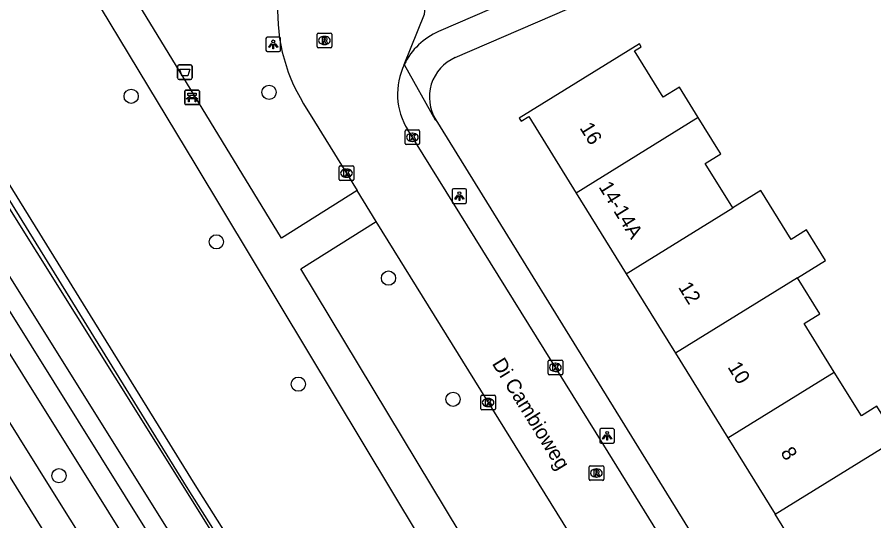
# Model space of a CAD drawing. Extents: x 159353 to 160616, y 385893 to 387321.
# Drawn here: x 159487.8 to 159546.6, y 386184 to 386218.6 of the extents above; entities that cross this region are included whole.
import ezdxf

# ---------------------------------------------------------------- set-up
doc = ezdxf.new("R2010")
doc.units = 0
for name, color, linetype in [('IMGEO_Afvalbak', 7, 'Continuous'), ('IMGEO_Bank', 7, 'Continuous'), ('IMGEO_Boom', 7, 'Continuous'), ('IMGEO_Fietspad_gesloten', 7, 'Continuous'), ('IMGEO_Haag', 7, 'Continuous'), ('IMGEO_Kolk', 7, 'Continuous'), ('IMGEO_Lichtpunt', 7, 'Continuous'), ('IMGEO_Openbare_ruimte_label', 7, 'Continuous'), ('IMGEO_Pand', 7, 'Continuous'), ('IMGEO_Pand_nummerreeks', 7, 'Continuous'), ('IMGEO_Rijbaan_lokaal_open', 7, 'Continuous'), ('IMGEO_Rioolput', 7, 'Continuous'), ('IMGEO_Voetpad_halfverhard', 7, 'Continuous'), ('IMGEO_Voetpad_open', 7, 'Continuous'), ('IMGEO_Waterloop', 7, 'Continuous')]:
    doc.layers.add(name, color=color, linetype=linetype)

msp = doc.modelspace()

# ---------------------------------------------------------------- linework, layer by layer
at = {"layer": 'IMGEO_Afvalbak'}
for p, q in [((159498.825, 386214.38), (159498.825, 386215.18)), ((159498.825, 386215.18), (159498.825, 386214.38)), ((159498.925, 386215.28), (159499.715, 386215.28)), ((159499.715, 386215.28), (159498.925, 386215.28)), ((159499.815, 386215.18), (159499.815, 386214.38)), ((159499.815, 386214.38), (159499.815, 386215.18)), ((159499.715, 386214.28), (159498.925, 386214.28)), ((159498.925, 386214.28), (159499.715, 386214.28))]:
    msp.add_line(p, q, dxfattribs=at)
msp.add_lwpolyline([(159498.968, 386214.994), (159499.672, 386214.994), (159499.523, 386214.524), (159499.117, 386214.524), (159498.968, 386214.994)], dxfattribs=at)
for centre, start, end in [((159498.925, 386215.18), 90, 180), ((159498.925, 386215.18), 90, 180), ((159499.715, 386215.18), 0, 90), ((159499.715, 386215.18), 360, 90), ((159498.925, 386214.38), 180, 270), ((159498.925, 386214.38), 180, 270), ((159499.715, 386214.38), 270, 0), ((159499.715, 386214.38), 270, 0)]:
    msp.add_arc(centre, 0.1, start, end, dxfattribs=at)
at = {"layer": 'IMGEO_Bank'}
for p, q in [((159499.318, 386212.627), (159499.318, 386213.468)), ((159499.318, 386213.468), (159499.318, 386212.627)), ((159499.393, 386213.552), (159500.234, 386213.552)), ((159500.234, 386213.552), (159499.393, 386213.552)), ((159500.318, 386213.477), (159500.318, 386212.636)), ((159500.318, 386212.636), (159500.318, 386213.477)), ((159500.015, 386212.95), (159499.622, 386212.95)), ((159499.627, 386213.058), (159499.627, 386213.164)), ((159499.671, 386213.164), (159499.671, 386213.058)), ((159499.959, 386213.17), (159499.677, 386213.17)), ((159499.677, 386213.052), (159499.959, 386213.052)), ((159499.965, 386213.058), (159499.965, 386213.164)), ((159500.009, 386213.164), (159500.009, 386213.058)), ((159500.243, 386212.552), (159499.402, 386212.552)), ((159499.402, 386212.552), (159500.243, 386212.552))]:
    msp.add_line(p, q, dxfattribs=at)
for points in [[(159499.621, 386213.17), (159499.535, 386213.17), (159499.535, 386213.331), (159500.098, 386213.331), (159500.098, 386213.17), (159500.015, 386213.17)], [(159499.565, 386212.95), (159499.423, 386212.95), (159499.535, 386213.052), (159499.621, 386213.052)], [(159499.615, 386212.943), (159499.615, 386212.736), (159499.572, 386212.736), (159499.572, 386212.943)], [(159500.015, 386213.052), (159500.098, 386213.052), (159500.21, 386212.95), (159500.071, 386212.95)], [(159500.065, 386212.943), (159500.065, 386212.736), (159500.021, 386212.736), (159500.021, 386212.943)]]:
    msp.add_lwpolyline(points, dxfattribs=at)
for centre, radius, start, end in [((159499.396, 386213.474), 0.0779, 92.4484, 184.28452), ((159499.396, 386213.474), 0.0779, 92.4484, 184.28452), ((159500.24, 386213.474), 0.0779, 2.4484, 94.28452), ((159500.24, 386213.474), 0.0779, 2.4484, 94.28452), ((159499.565, 386212.943), 0.00671, 2.89567, 87.10433), ((159499.622, 386212.943), 0.00671, 92.89567, 177.10433), ((159499.62, 386213.163), 0.00671, 2.89567, 87.10433), ((159499.62, 386213.059), 0.00671, 272.89567, 357.10433), ((159499.677, 386213.163), 0.00671, 92.89567, 177.10433), ((159499.677, 386213.059), 0.00671, 182.89567, 267.10433), ((159499.959, 386213.163), 0.00671, 2.89567, 87.10433), ((159499.959, 386213.059), 0.00671, 272.89567, 357.10433), ((159500.016, 386213.163), 0.00671, 92.89567, 177.10433), ((159500.016, 386213.059), 0.00671, 182.89567, 267.10433), ((159500.014, 386212.943), 0.00671, 2.89567, 87.10433), ((159500.071, 386212.943), 0.00671, 92.89567, 177.10433), ((159499.396, 386212.63), 0.0779, 182.4484, 274.28452), ((159499.396, 386212.63), 0.0779, 182.4484, 274.28452), ((159500.24, 386212.63), 0.0779, 272.4484, 4.28452), ((159500.24, 386212.63), 0.0779, 272.4484, 4.28452)]:
    msp.add_arc(centre, radius, start, end, dxfattribs=at)
at = {"layer": 'IMGEO_Boom'}
for centre in [(159505.097, 386213.396), (159495.642, 386213.127), (159501.485, 386203.148), (159513.283, 386200.66), (159507.104, 386193.391), (159517.712, 386192.355), (159490.692, 386187.113)]:
    msp.add_circle(centre, 0.489, dxfattribs=at)
at = {"layer": 'IMGEO_Fietspad_gesloten'}
for points in [[(159358.992, 386396.356), (159358.992, 386396.356), (159359.467, 386395.596), (159381.824, 386359.807), (159396.397, 386336.533), (159416.709, 386303.89), (159434.509, 386275.359), (159450.358, 386250), (159490.603, 386185.487), (159500, 386170.463), (159500.342, 386169.916), (159512.48, 386150.408), (159515.059, 386146.301), (159542.856, 386101.021), (159544.684, 386098.275)], [(159460.945, 386229.331), (159474.127, 386208.217), (159500, 386166.602), (159501.671, 386163.914), (159504.636, 386159.124), (159513.312, 386145.273), (159516.297, 386140.507), (159529.62, 386119.165), (159540.136, 386102.059), (159543.051, 386097.27)]]:
    msp.add_lwpolyline(points, dxfattribs=at)
at = {"layer": 'IMGEO_Haag'}
for points in [[(159382.354, 386376.783), (159419.283, 386316.377), (159458.061, 386254.291), (159460.741, 386250), (159500, 386186.48), (159520.962, 386153.341), (159520.51, 386153.027)], [(159381.896, 386376.477), (159418.815, 386316.088), (159457.595, 386254), (159460.274, 386249.71), (159499.534, 386186.188), (159520.51, 386153.027)]]:
    msp.add_lwpolyline(points, dxfattribs=at)
at = {"layer": 'IMGEO_Kolk'}
for p, q in [((159514.419, 386209.888), (159514.419, 386210.74)), ((159514.494, 386210.814), (159515.346, 386210.814)), ((159514.907, 386210.594), (159514.932, 386210.594)), ((159515.42, 386210.74), (159515.42, 386209.888)), ((159515.346, 386209.814), (159514.494, 386209.814)), ((159514.93, 386210.034), (159514.905, 386210.034)), ((159509.904, 386207.428), (159509.904, 386208.28)), ((159509.979, 386208.354), (159510.831, 386208.354)), ((159510.392, 386208.134), (159510.417, 386208.134)), ((159510.905, 386208.28), (159510.905, 386207.428)), ((159510.415, 386207.574), (159510.39, 386207.574)), ((159510.831, 386207.354), (159509.979, 386207.354)), ((159524.225, 386194.114), (159524.225, 386194.966)), ((159524.3, 386195.04), (159525.152, 386195.04)), ((159524.713, 386194.82), (159524.738, 386194.82)), ((159525.226, 386194.966), (159525.226, 386194.114)), ((159525.152, 386194.04), (159524.3, 386194.04)), ((159524.736, 386194.26), (159524.711, 386194.26)), ((159519.615, 386191.702), (159519.615, 386192.554)), ((159519.69, 386192.628), (159520.542, 386192.628)), ((159520.103, 386192.408), (159520.128, 386192.408)), ((159520.616, 386192.554), (159520.616, 386191.702)), ((159520.542, 386191.628), (159519.69, 386191.628)), ((159520.126, 386191.848), (159520.101, 386191.848))]:
    msp.add_line(p, q, dxfattribs=at)
for points in [[(159514.419, 386209.888), (159514.419, 386210.74)], [(159514.494, 386210.814), (159515.346, 386210.814)], [(159514.74, 386210.514), (159514.863, 386210.514), (159514.863, 386210.363), (159514.993, 386210.514), (159515.157, 386210.514), (159515.011, 386210.363), (159515.164, 386210.114), (159515.012, 386210.114), (159514.927, 386210.278), (159514.863, 386210.211), (159514.863, 386210.114), (159514.74, 386210.114), (159514.74, 386210.514)], [(159515.42, 386210.74), (159515.42, 386209.888)], [(159515.346, 386209.814), (159514.494, 386209.814)], [(159509.904, 386207.428), (159509.904, 386208.28)], [(159509.979, 386208.354), (159510.831, 386208.354)], [(159510.225, 386208.054), (159510.348, 386208.054), (159510.348, 386207.903), (159510.478, 386208.054), (159510.642, 386208.054), (159510.496, 386207.903), (159510.649, 386207.654), (159510.497, 386207.654), (159510.412, 386207.818), (159510.348, 386207.751), (159510.348, 386207.654), (159510.225, 386207.654), (159510.225, 386208.054)], [(159510.905, 386208.28), (159510.905, 386207.428)], [(159510.831, 386207.354), (159509.979, 386207.354)], [(159524.225, 386194.114), (159524.225, 386194.966)], [(159524.3, 386195.04), (159525.152, 386195.04)], [(159524.546, 386194.74), (159524.669, 386194.74), (159524.669, 386194.589), (159524.799, 386194.74), (159524.963, 386194.74), (159524.817, 386194.589), (159524.97, 386194.34), (159524.818, 386194.34), (159524.733, 386194.504), (159524.669, 386194.437), (159524.669, 386194.34), (159524.546, 386194.34), (159524.546, 386194.74)], [(159525.226, 386194.966), (159525.226, 386194.114)], [(159525.152, 386194.04), (159524.3, 386194.04)], [(159519.615, 386191.702), (159519.615, 386192.554)], [(159519.69, 386192.628), (159520.542, 386192.628)], [(159519.936, 386192.328), (159520.059, 386192.328), (159520.059, 386192.177), (159520.189, 386192.328), (159520.353, 386192.328), (159520.207, 386192.177), (159520.36, 386191.928), (159520.208, 386191.928), (159520.123, 386192.092), (159520.059, 386192.025), (159520.059, 386191.928), (159519.936, 386191.928), (159519.936, 386192.328)], [(159520.616, 386192.554), (159520.616, 386191.702)], [(159520.542, 386191.628), (159519.69, 386191.628)]]:
    msp.add_lwpolyline(points, dxfattribs=at)
for centre, start, end in [((159514.496, 386210.738), 91.55205, 178.44795), ((159514.496, 386210.738), 91.55205, 178.44795), ((159515.344, 386210.738), 1.55205, 88.44795), ((159515.344, 386210.738), 1.55205, 88.44795), ((159514.496, 386209.89), 181.55205, 268.44795), ((159514.496, 386209.89), 181.55205, 268.44795), ((159515.344, 386209.89), 271.55205, 358.44795), ((159515.344, 386209.89), 271.55205, 358.44795), ((159509.981, 386208.278), 91.55205, 178.44795), ((159509.981, 386208.278), 91.55205, 178.44795), ((159510.829, 386208.278), 1.55205, 88.44795), ((159510.829, 386208.278), 1.55205, 88.44795), ((159509.981, 386207.43), 181.55205, 268.44795), ((159509.981, 386207.43), 181.55205, 268.44795), ((159510.829, 386207.43), 271.55205, 358.44795), ((159510.829, 386207.43), 271.55205, 358.44795), ((159524.302, 386194.964), 91.55205, 178.44795), ((159524.302, 386194.964), 91.55205, 178.44795), ((159525.15, 386194.964), 1.55205, 88.44795), ((159525.15, 386194.964), 1.55205, 88.44795), ((159524.302, 386194.116), 181.55205, 268.44795), ((159524.302, 386194.116), 181.55205, 268.44795), ((159525.15, 386194.116), 271.55205, 358.44795), ((159525.15, 386194.116), 271.55205, 358.44795), ((159519.692, 386192.552), 91.55205, 178.44795), ((159519.692, 386192.552), 91.55205, 178.44795), ((159520.54, 386192.552), 1.55205, 88.44795), ((159520.54, 386192.552), 1.55205, 88.44795), ((159519.692, 386191.704), 181.55205, 268.44795), ((159519.692, 386191.704), 181.55205, 268.44795), ((159520.54, 386191.704), 271.55205, 358.44795), ((159520.54, 386191.704), 271.55205, 358.44795)]:
    msp.add_arc(centre, 0.0765, start, end, dxfattribs=at)
for centre, major_axis, ratio, start_param, end_param in [((159514.906, 386210.314), (-0.387, 0.002), 0.722429, 4.712389, 7.853982), ((159514.931, 386210.314), (-0.39, 0.002), 0.717154, 1.570796, 4.712389), ((159510.391, 386207.854), (-0.387, 0.002), 0.722429, 4.712389, 7.853982), ((159510.416, 386207.854), (-0.39, 0.002), 0.717154, 1.570796, 4.712389), ((159524.712, 386194.54), (-0.387, 0.002), 0.722429, 4.712389, 7.853982), ((159524.737, 386194.54), (-0.39, 0.002), 0.717154, 1.570796, 4.712389), ((159520.102, 386192.128), (-0.387, 0.002), 0.722429, 4.712389, 7.853982), ((159520.127, 386192.128), (-0.39, 0.002), 0.717154, 1.570796, 4.712389)]:
    msp.add_ellipse(centre, major_axis=major_axis, ratio=ratio, start_param=start_param, end_param=end_param, dxfattribs=at)
at = {"layer": 'IMGEO_Lichtpunt'}
for p, q in [((159504.883, 386217.087), (159504.883, 386216.28)), ((159504.883, 386217.087), (159504.883, 386216.28)), ((159505.785, 386217.182), (159504.977, 386217.182)), ((159505.785, 386217.182), (159504.977, 386217.182)), ((159505.879, 386216.28), (159505.879, 386217.087)), ((159505.879, 386216.28), (159505.879, 386217.087)), ((159504.977, 386216.186), (159505.785, 386216.186)), ((159504.977, 386216.186), (159505.785, 386216.186)), ((159517.646, 386206.686), (159517.646, 386205.879)), ((159517.646, 386206.686), (159517.646, 386205.879)), ((159518.548, 386206.781), (159517.74, 386206.781)), ((159518.548, 386206.781), (159517.74, 386206.781)), ((159518.642, 386205.879), (159518.642, 386206.686)), ((159518.642, 386205.879), (159518.642, 386206.686)), ((159517.74, 386205.785), (159518.548, 386205.785)), ((159517.74, 386205.785), (159518.548, 386205.785)), ((159527.775, 386190.249), (159527.775, 386189.442)), ((159527.775, 386190.249), (159527.775, 386189.442)), ((159528.677, 386190.344), (159527.869, 386190.344)), ((159528.677, 386190.344), (159527.869, 386190.344)), ((159528.771, 386189.442), (159528.771, 386190.249)), ((159528.771, 386189.442), (159528.771, 386190.249)), ((159527.869, 386189.348), (159528.677, 386189.348)), ((159527.869, 386189.348), (159528.677, 386189.348))]:
    msp.add_line(p, q, dxfattribs=at)
for points in [[(159505.257, 386216.751), (159505.296, 386216.723), (159505.108, 386216.461), (159505.07, 386216.488), (159505.257, 386216.751)], [(159505.359, 386216.703), (159505.406, 386216.703), (159505.406, 386216.381), (159505.359, 386216.381), (159505.359, 386216.703)], [(159505.469, 386216.723), (159505.507, 386216.75), (159505.694, 386216.488), (159505.655, 386216.46), (159505.469, 386216.723)], [(159518.02, 386206.35), (159518.059, 386206.322), (159517.871, 386206.06), (159517.833, 386206.087), (159518.02, 386206.35)], [(159518.122, 386206.302), (159518.169, 386206.302), (159518.169, 386205.98), (159518.122, 386205.98), (159518.122, 386206.302)], [(159518.232, 386206.322), (159518.27, 386206.349), (159518.457, 386206.087), (159518.418, 386206.059), (159518.232, 386206.322)], [(159528.149, 386189.913), (159528.188, 386189.885), (159528, 386189.623), (159527.962, 386189.65), (159528.149, 386189.913)], [(159528.251, 386189.865), (159528.298, 386189.865), (159528.298, 386189.543), (159528.251, 386189.543), (159528.251, 386189.865)], [(159528.361, 386189.885), (159528.399, 386189.912), (159528.586, 386189.65), (159528.547, 386189.622), (159528.361, 386189.885)]]:
    msp.add_lwpolyline(points, dxfattribs=at)
for centre in [(159505.382, 386216.885), (159518.145, 386206.484), (159528.274, 386190.047)]:
    msp.add_circle(centre, 0.0994, dxfattribs=at)
for centre, start, end in [((159504.977, 386217.087), 90, 180), ((159504.977, 386217.087), 90, 180), ((159505.785, 386217.087), 0, 90), ((159505.785, 386217.087), 0, 90), ((159504.977, 386216.28), 180, 270), ((159504.977, 386216.28), 180, 270), ((159505.785, 386216.28), 270, 0), ((159505.785, 386216.28), 270, 360), ((159517.74, 386206.686), 90, 180), ((159517.74, 386206.686), 90, 180), ((159518.548, 386206.686), 0, 90), ((159518.548, 386206.686), 0, 90), ((159517.74, 386205.879), 180, 270), ((159517.74, 386205.879), 180, 270), ((159518.548, 386205.879), 270, 0), ((159518.548, 386205.879), 270, 360), ((159527.869, 386190.249), 90, 180), ((159527.869, 386190.249), 90, 180), ((159528.677, 386190.249), 0, 90), ((159528.677, 386190.249), 0, 90), ((159527.869, 386189.442), 180, 270), ((159527.869, 386189.442), 180, 270), ((159528.677, 386189.442), 270, 0), ((159528.677, 386189.442), 270, 360)]:
    msp.add_arc(centre, 0.0946, start, end, dxfattribs=at)
at = {"layer": 'IMGEO_Pand'}
for points in [[(159534.522, 386211.671), (159533.226, 386213.759), (159532.116, 386213.072), (159530.157, 386216.238), (159530.61, 386216.519), (159530.486, 386216.721), (159522.251, 386211.626), (159522.379, 386211.419), (159522.909, 386211.746), (159526.159, 386206.494)], [(159534.522, 386211.671), (159526.159, 386206.494)], [(159536.881, 386205.471), (159534.998, 386208.513), (159536.07, 386209.177), (159535.863, 386209.511), (159534.522, 386211.671)], [(159526.159, 386206.494), (159529.585, 386200.956)], [(159541.325, 386200.685), (159543.251, 386201.877), (159541.953, 386203.973), (159540.889, 386203.314), (159538.814, 386206.667), (159536.881, 386205.471)], [(159529.585, 386200.956), (159536.881, 386205.471)], [(159529.585, 386200.956), (159532.957, 386195.506)], [(159541.325, 386200.685), (159532.957, 386195.506)], [(159543.84, 386194.224), (159541.786, 386197.543), (159542.858, 386198.207), (159541.325, 386200.685)], [(159532.957, 386195.506), (159536.545, 386189.708)], [(159536.545, 386189.708), (159543.84, 386194.224)], [(159548.154, 386189.648), (159546.773, 386191.88), (159545.702, 386191.217), (159543.84, 386194.224)], [(159536.545, 386189.708), (159539.786, 386184.469)], [(159539.786, 386184.469), (159548.154, 386189.648)], [(159543.292, 386178.802), (159539.786, 386184.469)]]:
    msp.add_lwpolyline(points, dxfattribs=at)
at = {"layer": 'IMGEO_Rijbaan_lokaal_open'}
for points in [[(159546.193, 386230.352), (159541.954, 386228.536), (159532.505, 386224.388), (159516.717, 386217.56)], [(159514.369, 386215.31), (159515.748, 386218.75), (159516.266, 386223.718), (159515.759, 386226.271), (159514.793, 386228.858)], [(159507.467, 386212.616), (159508.214, 386211.406), (159511.141, 386206.664)], [(159543.479, 386164.305), (159528.036, 386189.214), (159514.607, 386210.815)], [(159512.438, 386204.54), (159511.141, 386206.664)], [(159539.198, 386161.413), (159512.438, 386204.54)]]:
    msp.add_lwpolyline(points, dxfattribs=at)
for centre, radius, start, end in [((159517.645, 386218.896), 11.96, 174.8306, 211.67561), ((159518.565, 386213.281), 4.661, 113.36321, 154.1948), ((159518.567, 386213.278), 4.663, 154.17404, 211.88766)]:
    msp.add_arc(centre, radius, start, end, dxfattribs=at)
at = {"layer": 'IMGEO_Rioolput'}
for p, q in [((159508.465, 386217.454), (159509.317, 386217.454)), ((159508.39, 386216.528), (159508.39, 386217.38)), ((159508.878, 386217.234), (159508.903, 386217.234)), ((159509.391, 386217.38), (159509.391, 386216.528)), ((159509.317, 386216.454), (159508.465, 386216.454)), ((159508.901, 386216.674), (159508.876, 386216.674)), ((159527.035, 386186.872), (159527.035, 386187.724)), ((159527.11, 386187.798), (159527.962, 386187.798)), ((159527.523, 386187.578), (159527.548, 386187.578)), ((159528.036, 386187.724), (159528.036, 386186.872)), ((159527.546, 386187.018), (159527.521, 386187.018)), ((159527.962, 386186.798), (159527.11, 386186.798))]:
    msp.add_line(p, q, dxfattribs=at)
for points in [[(159508.465, 386217.454), (159509.317, 386217.454)], [(159508.39, 386216.528), (159508.39, 386217.38)], [(159508.979, 386217.152), (159508.727, 386217.154), (159508.727, 386216.754)], [(159508.727, 386216.754), (159508.851, 386216.754), (159508.851, 386216.916), (159508.862, 386216.916)], [(159508.905, 386217.073), (159508.851, 386217.073), (159508.851, 386216.992)], [(159508.851, 386216.992), (159508.903, 386216.992)], [(159508.909, 386216.887), (159508.98, 386216.754), (159509.12, 386216.754), (159509.055, 386216.88)], [(159509.391, 386217.38), (159509.391, 386216.528)], [(159509.317, 386216.454), (159508.465, 386216.454)], [(159527.035, 386186.872), (159527.035, 386187.724)], [(159527.11, 386187.798), (159527.962, 386187.798)], [(159527.624, 386187.496), (159527.372, 386187.498), (159527.372, 386187.098)], [(159528.036, 386187.724), (159528.036, 386186.872)], [(159527.372, 386187.098), (159527.496, 386187.098), (159527.496, 386187.26), (159527.507, 386187.26)], [(159527.55, 386187.417), (159527.496, 386187.417), (159527.496, 386187.336)], [(159527.496, 386187.336), (159527.548, 386187.336)], [(159527.554, 386187.231), (159527.625, 386187.098), (159527.765, 386187.098), (159527.7, 386187.224)], [(159527.962, 386186.798), (159527.11, 386186.798)]]:
    msp.add_lwpolyline(points, dxfattribs=at)
for centre, radius, start, end in [((159508.467, 386217.378), 0.0765, 91.55205, 178.44795), ((159508.467, 386217.378), 0.0765, 91.55205, 178.44795), ((159509.315, 386217.378), 0.0765, 1.55205, 88.44795), ((159509.315, 386217.378), 0.0765, 1.55205, 88.44795), ((159508.861, 386216.863), 0.0533, 26.02933, 88.69889), ((159508.887, 386217.181), 0.19, 274.7715, 282.96867), ((159508.911, 386216.977), 0.0964, 77.00612, 93.18647), ((159508.925, 386217.034), 0.0378, 276.66336, 79.67722), ((159508.978, 386217.042), 0.109, 350.36119, 89.41601), ((159508.976, 386217.042), 0.112, 277.58423, 350.98172), ((159508.96, 386216.827), 0.108, 29.51342, 73.79051), ((159508.467, 386216.53), 0.0765, 181.55205, 268.44795), ((159508.467, 386216.53), 0.0765, 181.55205, 268.44795), ((159509.315, 386216.53), 0.0765, 271.55205, 358.44795), ((159509.315, 386216.53), 0.0765, 271.55205, 358.44795), ((159527.112, 386187.722), 0.0765, 91.55205, 178.44795), ((159527.112, 386187.722), 0.0765, 91.55205, 178.44795), ((159527.623, 386187.386), 0.109, 350.36119, 89.41601), ((159527.96, 386187.722), 0.0765, 1.55205, 88.44795), ((159527.96, 386187.722), 0.0765, 1.55205, 88.44795), ((159527.112, 386186.874), 0.0765, 181.55205, 268.44795), ((159527.112, 386186.874), 0.0765, 181.55205, 268.44795), ((159527.506, 386187.207), 0.0533, 26.02933, 88.69889), ((159527.532, 386187.525), 0.19, 274.7715, 282.96867), ((159527.556, 386187.321), 0.0964, 77.00612, 93.18647), ((159527.57, 386187.378), 0.0378, 276.66336, 79.67722), ((159527.621, 386187.386), 0.112, 277.58423, 350.98172), ((159527.605, 386187.171), 0.108, 29.51342, 73.79051), ((159527.96, 386186.874), 0.0765, 271.55205, 358.44795), ((159527.96, 386186.874), 0.0765, 271.55205, 358.44795)]:
    msp.add_arc(centre, radius, start, end, dxfattribs=at)
for centre, major_axis, ratio, start_param, end_param in [((159508.877, 386216.954), (-0.387, 0.002), 0.722429, 4.712389, 7.853982), ((159508.902, 386216.954), (-0.39, 0.002), 0.717154, 1.570796, 4.712389), ((159527.522, 386187.298), (-0.387, 0.002), 0.722429, 4.712389, 7.853982), ((159527.547, 386187.298), (-0.39, 0.002), 0.717154, 1.570796, 4.712389)]:
    msp.add_ellipse(centre, major_axis=major_axis, ratio=ratio, start_param=start_param, end_param=end_param, dxfattribs=at)
at = {"layer": 'IMGEO_Voetpad_halfverhard'}
for points in [[(159511.141, 386206.664), (159505.958, 386203.39), (159500, 386213.135), (159492.338, 386225.714), (159500, 386230.51), (159505.546, 386233.961)], [(159497.07, 386231.661), (159489.026, 386226.714), (159500, 386208.498), (159528.806, 386160.626), (159537.188, 386146.961), (159537.348, 386146.745)], [(159530.458, 386162.806), (159530.123, 386163.377), (159507.269, 386201.293), (159512.438, 386204.54)]]:
    msp.add_lwpolyline(points, dxfattribs=at)
at = {"layer": 'IMGEO_Voetpad_open'}
for points in [[(159361.592, 386399.829), (159362.056, 386399.085), (159455.092, 386250), (159500, 386178.036), (159518.514, 386148.338)], [(159548.371, 386097.594), (159545.848, 386101.702), (159531.743, 386124.354), (159519.361, 386144.039), (159517.175, 386147.549), (159507.63, 386162.875), (159501.77, 386172.355), (159500, 386175.187), (159458.712, 386241.251), (159453.256, 386250), (159435.15, 386279.032), (159415.41, 386310.673), (159399.888, 386335.332), (159389.058, 386352.807), (159376.566, 386372.971), (159363.439, 386393.878), (159361.065, 386397.75), (159360.601, 386398.506)], [(159517.863, 386215.778), (159545.705, 386227.831)], [(159514.369, 386215.31), (159516.495, 386211.518), (159516.528, 386211.509)], [(159516.528, 386211.509), (159545.289, 386164.985)]]:
    msp.add_lwpolyline(points, dxfattribs=at)
msp.add_arc((159519.046, 386213.065), 2.96, 113.55974, 211.70928, dxfattribs=at)
at = {"layer": 'IMGEO_Waterloop'}
for points in [[(159519.603, 386148.98), (159500, 386180.471), (159456.532, 386250), (159379.941, 386372.509), (159362.875, 386400.189), (159362.418, 386400.931), (159362.418, 386400.931)], [(159521.718, 386150.228), (159500, 386185.135), (159459.428, 386250), (159428.317, 386299.74), (159381.378, 386376.132)]]:
    msp.add_lwpolyline(points, dxfattribs=at)

# ---------------------------------------------------------------- texts
at = {"layer": 'IMGEO_Openbare_ruimte_label'}
msp.add_text('Di Cambioweg', height=1, rotation=301.79891, dxfattribs=at).set_placement((159520.351, 386194.801))
at = {"layer": 'IMGEO_Pand_nummerreeks'}
for s, rotation, p in [('16', 301.7464, (159526.356, 386210.964)), ('14-14A', 301.74165, (159527.66, 386206.918)), ('12', 301.74738, (159533.119, 386200.033)), ('10', 301.7464, (159536.504, 386194.562)), ('8', 301.7464, (159540.13, 386188.703))]:
    msp.add_text(s, height=1, rotation=rotation, dxfattribs=at).set_placement(p)

doc.saveas('drawing.dxf')
